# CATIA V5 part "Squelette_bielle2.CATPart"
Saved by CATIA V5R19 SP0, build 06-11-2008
Part number: Squelette_bielle2
Bounding box of the stored display mesh (mm): x -500 to 500, y -158.201 to 2099.603, z 224.486 to 2248.181
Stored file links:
  C:\Users\Guillaume et Fanny\Documents\IFMA\2A\IAO\Squelette_bielle2.CATPart
  C:\Users\Guillaume et Fanny\Documents\IFMA\2A\IAO\Train d'aterrissage.CATProduct
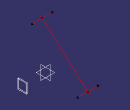
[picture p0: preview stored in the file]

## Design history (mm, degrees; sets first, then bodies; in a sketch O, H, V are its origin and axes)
Set1
  Point1: linked copy from another document
  Point2: linked copy from another document
Body1 (main body)
  Line1: type PtDir, Direction (1, 0, 0), Start -500, End 500, RefPoint Point1
  Line2: type PtDir, Direction (1, 0, 0), Start -500, End 500, RefPoint Point2
  Line3: type PtPt, SecondPoint Point1, FirstPoint Point2
  Plane1 "Plan.1170": type Offset, Offset 1170, RefPlane yz-plane
  Plane2 "Plan.1120": type Offset, Offset 1120, RefPlane yz-plane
